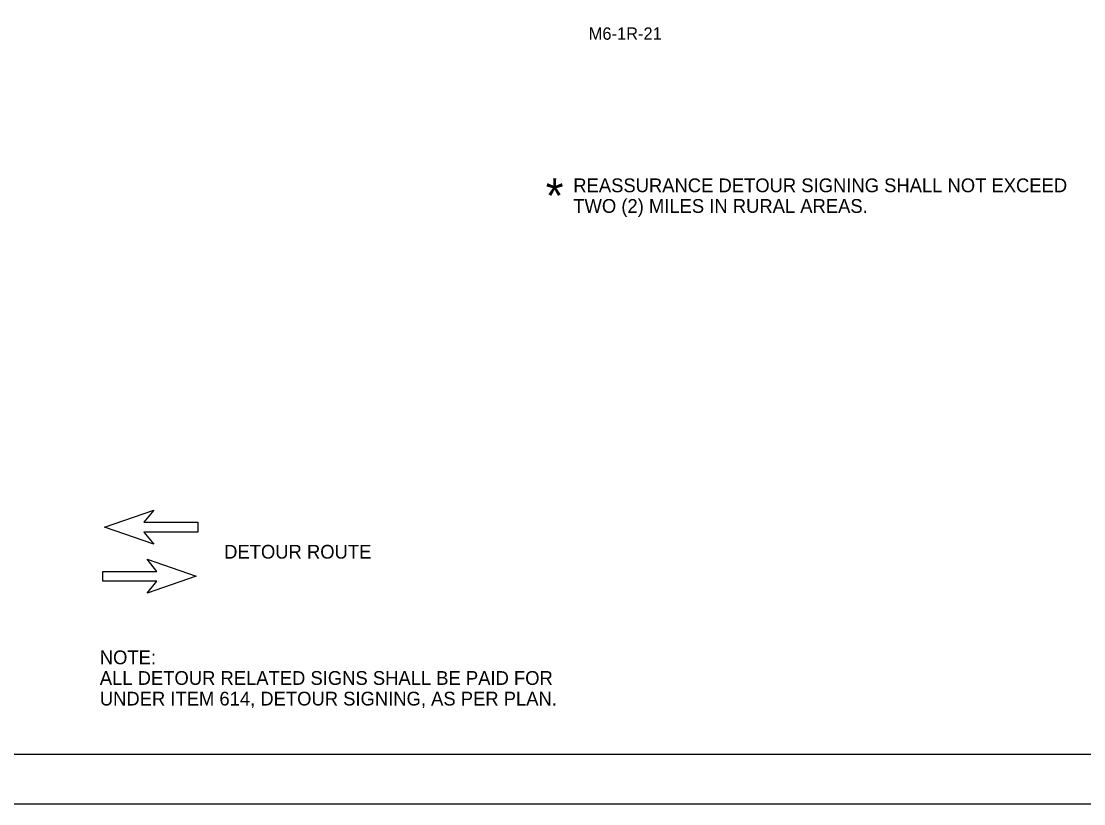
# Model space of a CAD drawing. Extents: x -0.3 to 34, y 0 to 22.
# Drawn here: x 16.2 to 27.01, y 0 to 7.96 of the extents above; entities that cross this region are included whole.
import ezdxf

# ---------------------------------------------------------------- set-up
doc = ezdxf.new("R2010")
doc.units = 0
for name, color, linetype in [('GM_X_Adjacent_County_Text', 7, 'Continuous'), ('GM_X_County', 7, 'Continuous'), ('GM_X_Minor_Lake_Text', 7, 'Continuous'), ('GM_X_Minor_River', 7, 'Continuous'), ('GM_X_Section', 7, 'Continuous')]:
    doc.layers.add(name, color=color, linetype=linetype)

msp = doc.modelspace()

# ---------------------------------------------------------------- linework, layer by layer
at = {"layer": 'GM_X_County'}
msp.add_lwpolyline([(1.5, 21.5), (33.5, 21.5), (33.5, 0.5), (1.5, 0.5)], close=True, dxfattribs=at)
at = {"layer": 'GM_X_Minor_River'}
for p, q in [((17.048, 2.815), (17.548, 2.989)), ((17.548, 2.989), (17.448, 2.865)), ((17.048, 2.815), (17.048, 2.815)), ((17.548, 2.642), (17.048, 2.815)), ((17.448, 2.865), (17.998, 2.865)), ((17.998, 2.865), (17.998, 2.765)), ((17.998, 2.815), (17.998, 2.815)), ((17.998, 2.765), (17.448, 2.765)), ((17.448, 2.765), (17.548, 2.642)), ((17.581, 2.365), (17.481, 2.489)), ((17.481, 2.489), (17.981, 2.315)), ((17.031, 2.265), (17.031, 2.365)), ((17.031, 2.365), (17.581, 2.365)), ((17.031, 2.315), (17.031, 2.315)), ((17.981, 2.315), (17.481, 2.142)), ((17.981, 2.315), (17.981, 2.315)), ((17.581, 2.265), (17.031, 2.265)), ((17.481, 2.142), (17.581, 2.265))]:
    msp.add_line(p, q, dxfattribs=at)
at = {"layer": 'GM_X_Section'}
msp.add_lwpolyline([(0, 0), (34, 0), (34, 22), (0, 22)], close=True, dxfattribs=at)

# ---------------------------------------------------------------- texts
at = {"layer": 'GM_X_Adjacent_County_Text'}
for s, height, p in [('*', 0.35, (21.536, 6.014)), ('REASSURANCE DETOUR SIGNING SHALL NOT EXCEED', 0.14, (21.817, 6.224)), ('TWO (2) MILES IN RURAL AREAS.', 0.14, (21.817, 6.014)), ('DETOUR ROUTE', 0.14, (18.265, 2.495)), ('NOTE:', 0.14, (17, 1.42)), ('ALL DETOUR RELATED SIGNS SHALL BE PAID FOR', 0.14, (17, 1.21)), ('UNDER ITEM 614, DETOUR SIGNING, AS PER PLAN.', 0.14, (17, 1))]:
    msp.add_text(s, height=height, dxfattribs=at).set_placement(p)
at = {"layer": 'GM_X_Minor_Lake_Text'}
msp.add_text('M6-1R-21', height=0.125, dxfattribs=at).set_placement((21.974, 7.776))

doc.saveas('drawing.dxf')
